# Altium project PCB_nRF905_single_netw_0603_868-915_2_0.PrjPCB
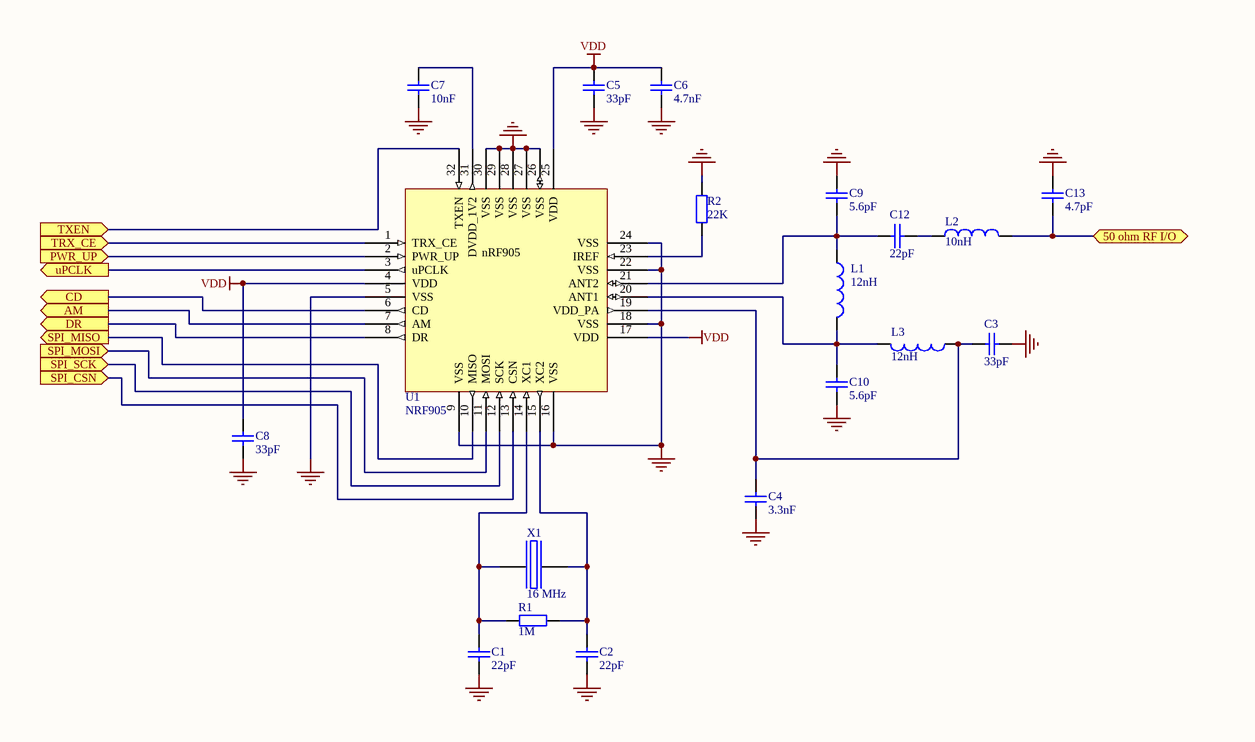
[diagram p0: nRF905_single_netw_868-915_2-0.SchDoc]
1 sheet, 19 parts. Net scope: flat (ports and power ports of the same name join across sheets).
Board file: nRF905_single_netw_0603_868-915_2-0.PcbDoc

## Sheet nRF905_single_netw_868-915_2-0.SchDoc: nRF905 diff. to single ended matching network 868/915MHz
size A4; Organization: Nordic VLSI ASA; Address1: Vestre Rosten 81; Address2: N-7075 Tiller; Address3: Norway; Revision: 2.0; SheetNumber: 1; SheetTotal: 1

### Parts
C1  22pF  [0603s]
C2  22pF  [0603s]
C3  33pF  [0603s]
C4  3.3nF  [0603s]
C5  33pF  [0603s]
C6  4.7nF  [0603s]
C7  10nF  [0603s]
C8  33pF  [0603s]
C9  5.6pF  [0603s]
C10  5.6pF  [0603s]
C12  22pF  [0603s]
C13  4.7pF  [0603s]
L1  12nH  [0603s]
L2  10nH  [0603s]
L3  12nH  [0603s]
R1  1M  [0603s]
R2  22K  [0603s]
U1  NRF905  [QFN 5x5/32L]
X1  16 MHz  [BT-XTAL]

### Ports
50 ohm RF I/O (bidir), AM (out), CD (out), DR (out), PWR_UP (in), SPI_CSN (in), SPI_MISO (out), SPI_MOSI (in), SPI_SCK (in), TRX_CE (in), TXEN (in), uPCLK (out)

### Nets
GND: C1.2 C2.1 C3.2 C4.2 C5.2 C6.2 C7.1 C8.2 C9.2 C10.1 C13.2 R2.2 U1.5(VSS) U1.9(VSS) U1.16(VSS) U1.18(VSS) U1.22(VSS) U1.24(VSS) U1.26(VSS) U1.27(VSS) U1.28(VSS) U1.29(VSS) U1.30(VSS) X1.2(GND) X1.4(GND)
VDD: C5.1 C6.1 C8.1 U1.4(VDD) U1.17(VDD) U1.25(VDD)
NetC1_1: C1.1 R1.1 U1.14(XC1) X1.1(inp)
NetC2_2: C2.2 R1.2 U1.15(XC2) X1.3(out)
NetC3_1: C3.1 C4.1 L3.1 U1.19(VDD_PA)
NetC7_2: C7.2 U1.31(DVDD_1V2)
NetC9_1: C9.1 C12.1 L1.1 U1.21(ANT2)
NetC10_2: C10.2 L1.2 L3.2 U1.20(ANT1)
NetC12_2: C12.2 L2.1
NetC13_1: C13.1 L2.2 ; port 50 ohm RF I/O
NetR2_1: R2.1 U1.23(IREF)
NetU1_1: U1.1(TRX_CE) ; port TRX_CE
NetU1_2: U1.2(PWR_UP) ; port PWR_UP
NetU1_3: U1.3(uPCLK) ; port uPCLK
NetU1_6: U1.6(CD) ; port CD
NetU1_7: U1.7(AM) ; port AM
NetU1_8: U1.8(DR) ; port DR
NetU1_10: U1.10(MISO) ; port SPI_MISO
NetU1_11: U1.11(MOSI) ; port SPI_MOSI
NetU1_12: U1.12(SCK) ; port SPI_SCK
NetU1_13: U1.13(CSN) ; port SPI_CSN
NetU1_32: U1.32(TXEN) ; port TXEN

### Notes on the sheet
- aaaaaaaa

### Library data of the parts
C1-C10 C13 = Cap Semi: Capacitor (Semiconductor SIM Model)
C12 = CAP
L1-L3 = Inductor
R1 R2 = Res2: Resistor
U1 = NRF905: 433/868/915MHz Single Chip RF Transceiver
X1 = BT-XTAL: Part Field 1: 0603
